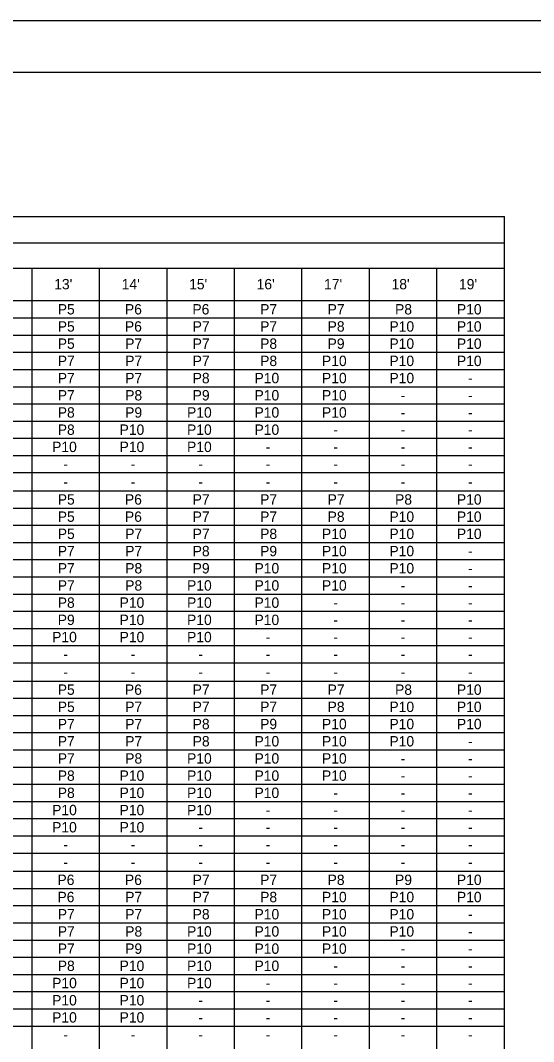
# Model space of a CAD drawing. Extents: x 637580 to 641008, y 294594 to 295782.
# Drawn here: x 639573.7 to 639722, y 295486.4 to 295781.6 of the extents above; entities that cross this region are included whole.
import ezdxf

# ---------------------------------------------------------------- set-up
doc = ezdxf.new("R2010")
doc.units = 0
for name, color, linetype in [('1', 7, 'Continuous'), ('2', 7, 'Continuous'), ('PLT-BNDY', 7, 'Continuous')]:
    doc.layers.add(name, color=color, linetype=linetype)

msp = doc.modelspace()

# ---------------------------------------------------------------- linework, layer by layer
at = {"layer": '1'}
for p, q in [((639302.31, 295766.63), (640088.31, 295766.63)), ((639346.67, 295724.98), (639713.6, 295724.98)), ((639713.6, 295260.68), (639713.6, 295724.98)), ((639346.67, 295717.3), (639713.6, 295717.3)), ((639346.67, 295700.6), (639713.6, 295700.6)), ((639346.67, 295645.61), (639713.6, 295645.61)), ((639346.67, 295590.62), (639713.6, 295590.62)), ((639346.67, 295535.63), (639713.6, 295535.63))]:
    msp.add_line(p, q, dxfattribs=at)
at = {"layer": '2'}
for p, q in [((639401.48, 295709.96), (639713.6, 295709.96)), ((639577.04, 295260.68), (639577.04, 295709.96)), ((639596.55, 295260.68), (639596.55, 295709.96)), ((639616.06, 295260.68), (639616.06, 295709.96)), ((639635.57, 295260.68), (639635.57, 295709.96)), ((639655.07, 295260.68), (639655.07, 295709.96)), ((639674.58, 295260.68), (639674.58, 295709.96)), ((639694.09, 295260.68), (639694.09, 295709.96)), ((639373.47, 295695.62), (639713.6, 295695.62)), ((639373.47, 295690.65), (639713.6, 295690.65)), ((639373.47, 295685.68), (639713.6, 295685.68)), ((639373.47, 295680.71), (639713.6, 295680.71)), ((639373.47, 295675.73), (639713.6, 295675.73)), ((639373.47, 295670.76), (639713.6, 295670.76)), ((639373.47, 295665.79), (639713.6, 295665.79)), ((639373.47, 295660.82), (639713.6, 295660.82)), ((639373.47, 295655.84), (639713.6, 295655.84)), ((639373.47, 295650.87), (639713.6, 295650.87)), ((639373.47, 295640.63), (639713.6, 295640.63)), ((639373.47, 295635.66), (639713.6, 295635.66)), ((639373.47, 295630.69), (639713.6, 295630.69)), ((639373.47, 295625.72), (639713.6, 295625.72)), ((639373.47, 295620.74), (639713.6, 295620.74)), ((639373.47, 295615.77), (639713.6, 295615.77)), ((639373.47, 295610.8), (639713.6, 295610.8)), ((639373.47, 295605.83), (639713.6, 295605.83)), ((639373.47, 295600.85), (639713.6, 295600.85)), ((639373.47, 295595.88), (639713.6, 295595.88)), ((639373.47, 295585.64), (639713.6, 295585.64)), ((639373.47, 295580.67), (639713.6, 295580.67)), ((639373.47, 295575.7), (639713.6, 295575.7)), ((639373.47, 295570.73), (639713.6, 295570.73)), ((639373.47, 295565.75), (639713.6, 295565.75)), ((639373.47, 295560.78), (639713.6, 295560.78)), ((639373.47, 295555.81), (639713.6, 295555.81)), ((639373.47, 295550.84), (639713.6, 295550.84)), ((639373.47, 295545.86), (639713.6, 295545.86)), ((639373.47, 295540.89), (639713.6, 295540.89)), ((639373.47, 295530.65), (639713.6, 295530.65)), ((639373.47, 295525.68), (639713.6, 295525.68)), ((639373.47, 295520.71), (639713.6, 295520.71)), ((639373.47, 295515.74), (639713.6, 295515.74)), ((639373.47, 295510.76), (639713.6, 295510.76)), ((639373.47, 295505.79), (639713.6, 295505.79)), ((639373.47, 295500.82), (639713.6, 295500.82)), ((639373.47, 295495.85), (639713.6, 295495.85)), ((639373.47, 295490.87), (639713.6, 295490.87))]:
    msp.add_line(p, q, dxfattribs=at)
at = {"layer": 'PLT-BNDY'}
msp.add_lwpolyline([(639262.31, 295781.63), (640103.31, 295781.63), (640103.31, 295187.63), (639262.31, 295187.63)], close=True, dxfattribs=at)

# ---------------------------------------------------------------- texts
at = {"layer": '1'}
for s, p in [("13'", (639583.43, 295703.87)), ("14'", (639602.94, 295703.87)), ("15'", (639622.44, 295703.87)), ("16'", (639641.95, 295703.87)), ("17'", (639661.46, 295703.87)), ("18'", (639680.97, 295703.87)), ("19'", (639700.47, 295703.87)), ('P5', (639584.45, 295696.61)), ('P6', (639603.87, 295696.61)), ('P6', (639623.38, 295696.61)), ('P7', (639642.97, 295696.61)), ('P7', (639662.48, 295696.61)), ('P8', (639681.98, 295696.61)), ('P10', (639699.86, 295696.61)), ('P5', (639584.45, 295691.64)), ('P6', (639603.87, 295691.64)), ('P7', (639623.46, 295691.64)), ('P7', (639642.97, 295691.64)), ('P8', (639662.48, 295691.64)), ('P10', (639680.35, 295691.64)), ('P10', (639699.86, 295691.64)), ('P5', (639584.45, 295686.67)), ('P7', (639603.95, 295686.67)), ('P7', (639623.46, 295686.67)), ('P8', (639642.97, 295686.67)), ('P9', (639662.47, 295686.67)), ('P10', (639680.35, 295686.67)), ('P10', (639699.86, 295686.67)), ('P7', (639584.45, 295681.69)), ('P7', (639603.95, 295681.69)), ('P7', (639623.46, 295681.69)), ('P8', (639642.97, 295681.69)), ('P10', (639660.85, 295681.69)), ('P10', (639680.35, 295681.69)), ('P10', (639699.86, 295681.69)), ('P7', (639584.45, 295676.72)), ('P7', (639603.95, 295676.72)), ('P8', (639623.46, 295676.72)), ('P10', (639641.34, 295676.72)), ('P10', (639660.85, 295676.72)), ('P10', (639680.35, 295676.72)), ('-', (639703.11, 295676.72)), ('P7', (639584.45, 295671.75)), ('P8', (639603.95, 295671.75)), ('P9', (639623.45, 295671.75)), ('P10', (639641.34, 295671.75)), ('P10', (639660.85, 295671.75)), ('-', (639683.6, 295671.75)), ('-', (639703.11, 295671.75)), ('P8', (639584.45, 295666.78)), ('P9', (639603.94, 295666.78)), ('P10', (639621.83, 295666.78)), ('P10', (639641.34, 295666.78)), ('P10', (639660.85, 295666.78)), ('-', (639683.6, 295666.78)), ('-', (639703.11, 295666.78)), ('P8', (639584.45, 295661.8)), ('P10', (639602.33, 295661.8)), ('P10', (639621.83, 295661.8)), ('P10', (639641.34, 295661.8)), ('-', (639664.1, 295661.8)), ('-', (639683.6, 295661.8)), ('-', (639703.11, 295661.8)), ('P10', (639582.82, 295656.83)), ('P10', (639602.33, 295656.83)), ('P10', (639621.83, 295656.83)), ('-', (639644.59, 295656.83)), ('-', (639664.1, 295656.83)), ('-', (639683.6, 295656.83)), ('-', (639703.11, 295656.83)), ('-', (639586.07, 295651.86)), ('-', (639605.57, 295651.86)), ('-', (639625.08, 295651.86)), ('-', (639644.59, 295651.86)), ('-', (639664.1, 295651.86)), ('-', (639683.6, 295651.86)), ('-', (639703.11, 295651.86)), ('-', (639586.07, 295646.74)), ('-', (639605.57, 295646.74)), ('-', (639625.08, 295646.74)), ('-', (639644.59, 295646.74)), ('-', (639664.1, 295646.74)), ('-', (639683.6, 295646.74)), ('-', (639703.11, 295646.74)), ('P5', (639584.45, 295641.62)), ('P6', (639603.87, 295641.62)), ('P7', (639623.46, 295641.62)), ('P7', (639642.97, 295641.62)), ('P7', (639662.48, 295641.62)), ('P8', (639681.98, 295641.62)), ('P10', (639699.86, 295641.62)), ('P5', (639584.45, 295636.65)), ('P6', (639603.87, 295636.65)), ('P7', (639623.46, 295636.65)), ('P7', (639642.97, 295636.65)), ('P8', (639662.48, 295636.65)), ('P10', (639680.35, 295636.65)), ('P10', (639699.86, 295636.65)), ('P5', (639584.45, 295631.68)), ('P7', (639603.95, 295631.68)), ('P7', (639623.46, 295631.68)), ('P8', (639642.97, 295631.68)), ('P10', (639660.85, 295631.68)), ('P10', (639680.35, 295631.68)), ('P10', (639699.86, 295631.68)), ('P7', (639584.45, 295626.7)), ('P7', (639603.95, 295626.7)), ('P8', (639623.46, 295626.7)), ('P9', (639642.96, 295626.7)), ('P10', (639660.85, 295626.7)), ('P10', (639680.35, 295626.7)), ('-', (639703.11, 295626.7)), ('P7', (639584.45, 295621.73)), ('P8', (639603.95, 295621.73)), ('P9', (639623.45, 295621.73)), ('P10', (639641.34, 295621.73)), ('P10', (639660.85, 295621.73)), ('P10', (639680.35, 295621.73)), ('-', (639703.11, 295621.73)), ('P7', (639584.45, 295616.76)), ('P8', (639603.95, 295616.76)), ('P10', (639621.83, 295616.76)), ('P10', (639641.34, 295616.76)), ('P10', (639660.85, 295616.76)), ('-', (639683.6, 295616.76)), ('-', (639703.11, 295616.76)), ('P8', (639584.45, 295611.79)), ('P10', (639602.33, 295611.79)), ('P10', (639621.83, 295611.79)), ('P10', (639641.34, 295611.79)), ('-', (639664.1, 295611.79)), ('-', (639683.6, 295611.79)), ('-', (639703.11, 295611.79)), ('P9', (639584.44, 295606.81)), ('P10', (639602.33, 295606.81)), ('P10', (639621.83, 295606.81)), ('P10', (639641.34, 295606.81)), ('-', (639664.1, 295606.81)), ('-', (639683.6, 295606.81)), ('-', (639703.11, 295606.81)), ('P10', (639582.82, 295601.84)), ('P10', (639602.33, 295601.84)), ('P10', (639621.83, 295601.84)), ('-', (639644.59, 295601.84)), ('-', (639664.1, 295601.84)), ('-', (639683.6, 295601.84)), ('-', (639703.11, 295601.84)), ('-', (639586.07, 295596.87)), ('-', (639605.57, 295596.87)), ('-', (639625.08, 295596.87)), ('-', (639644.59, 295596.87)), ('-', (639664.1, 295596.87)), ('-', (639683.6, 295596.87)), ('-', (639703.11, 295596.87)), ('-', (639586.07, 295591.75)), ('-', (639605.57, 295591.75)), ('-', (639625.08, 295591.75)), ('-', (639644.59, 295591.75)), ('-', (639664.1, 295591.75)), ('-', (639683.6, 295591.75)), ('-', (639703.11, 295591.75)), ('P5', (639584.45, 295586.63)), ('P6', (639603.87, 295586.63)), ('P7', (639623.46, 295586.63)), ('P7', (639642.97, 295586.63)), ('P7', (639662.48, 295586.63)), ('P8', (639681.98, 295586.63)), ('P10', (639699.86, 295586.63)), ('P5', (639584.45, 295581.66)), ('P7', (639603.95, 295581.66)), ('P7', (639623.46, 295581.66)), ('P7', (639642.97, 295581.66)), ('P8', (639662.48, 295581.66)), ('P10', (639680.35, 295581.66)), ('P10', (639699.86, 295581.66)), ('P7', (639584.45, 295576.69)), ('P7', (639603.95, 295576.69)), ('P8', (639623.46, 295576.69)), ('P9', (639642.96, 295576.69)), ('P10', (639660.85, 295576.69)), ('P10', (639680.35, 295576.69)), ('P10', (639699.86, 295576.69)), ('P7', (639584.45, 295571.71)), ('P7', (639603.95, 295571.71)), ('P8', (639623.46, 295571.71)), ('P10', (639641.34, 295571.71)), ('P10', (639660.85, 295571.71)), ('P10', (639680.35, 295571.71)), ('-', (639703.11, 295571.71)), ('P7', (639584.45, 295566.74)), ('P8', (639603.95, 295566.74)), ('P10', (639621.83, 295566.74)), ('P10', (639641.34, 295566.74)), ('P10', (639660.85, 295566.74)), ('-', (639683.6, 295566.74)), ('-', (639703.11, 295566.74)), ('P8', (639584.45, 295561.77)), ('P10', (639602.33, 295561.77)), ('P10', (639621.83, 295561.77)), ('P10', (639641.34, 295561.77)), ('P10', (639660.85, 295561.77)), ('-', (639683.6, 295561.77)), ('-', (639703.11, 295561.77)), ('P8', (639584.45, 295556.8)), ('P10', (639602.33, 295556.8)), ('P10', (639621.83, 295556.8)), ('P10', (639641.34, 295556.8)), ('-', (639664.1, 295556.8)), ('-', (639683.6, 295556.8)), ('-', (639703.11, 295556.8)), ('P10', (639582.82, 295551.82)), ('P10', (639602.33, 295551.82)), ('P10', (639621.83, 295551.82)), ('-', (639644.59, 295551.82)), ('-', (639664.1, 295551.82)), ('-', (639683.6, 295551.82)), ('-', (639703.11, 295551.82)), ('P10', (639582.82, 295546.85)), ('P10', (639602.33, 295546.85)), ('-', (639625.08, 295546.85)), ('-', (639644.59, 295546.85)), ('-', (639664.1, 295546.85)), ('-', (639683.6, 295546.85)), ('-', (639703.11, 295546.85)), ('-', (639586.07, 295541.88)), ('-', (639605.57, 295541.88)), ('-', (639625.08, 295541.88)), ('-', (639644.59, 295541.88)), ('-', (639664.1, 295541.88)), ('-', (639683.6, 295541.88)), ('-', (639703.11, 295541.88)), ('-', (639586.07, 295536.76)), ('-', (639605.57, 295536.76)), ('-', (639625.08, 295536.76)), ('-', (639644.59, 295536.76)), ('-', (639664.1, 295536.76)), ('-', (639683.6, 295536.76)), ('-', (639703.11, 295536.76)), ('P6', (639584.36, 295531.64)), ('P6', (639603.87, 295531.64)), ('P7', (639623.46, 295531.64)), ('P7', (639642.97, 295531.64)), ('P8', (639662.48, 295531.64)), ('P9', (639681.97, 295531.64)), ('P10', (639699.86, 295531.64)), ('P6', (639584.36, 295526.67)), ('P7', (639603.95, 295526.67)), ('P7', (639623.46, 295526.67)), ('P8', (639642.97, 295526.67)), ('P10', (639660.85, 295526.67)), ('P10', (639680.35, 295526.67)), ('P10', (639699.86, 295526.67)), ('P7', (639584.45, 295521.7)), ('P7', (639603.95, 295521.7)), ('P8', (639623.46, 295521.7)), ('P10', (639641.34, 295521.7)), ('P10', (639660.85, 295521.7)), ('P10', (639680.35, 295521.7)), ('-', (639703.11, 295521.7)), ('P7', (639584.45, 295516.72)), ('P8', (639603.95, 295516.72)), ('P10', (639621.83, 295516.72)), ('P10', (639641.34, 295516.72)), ('P10', (639660.85, 295516.72)), ('P10', (639680.35, 295516.72)), ('-', (639703.11, 295516.72)), ('P7', (639584.45, 295511.75)), ('P9', (639603.94, 295511.75)), ('P10', (639621.83, 295511.75)), ('P10', (639641.34, 295511.75)), ('P10', (639660.85, 295511.75)), ('-', (639683.6, 295511.75)), ('-', (639703.11, 295511.75)), ('P8', (639584.45, 295506.78)), ('P10', (639602.33, 295506.78)), ('P10', (639621.83, 295506.78)), ('P10', (639641.34, 295506.78)), ('-', (639664.1, 295506.78)), ('-', (639683.6, 295506.78)), ('-', (639703.11, 295506.78)), ('P10', (639582.82, 295501.81)), ('P10', (639602.33, 295501.81)), ('P10', (639621.83, 295501.81)), ('-', (639644.59, 295501.81)), ('-', (639664.1, 295501.81)), ('-', (639683.6, 295501.81)), ('-', (639703.11, 295501.81)), ('P10', (639582.82, 295496.83)), ('P10', (639602.33, 295496.83)), ('-', (639625.08, 295496.83)), ('-', (639644.59, 295496.83)), ('-', (639664.1, 295496.83)), ('-', (639683.6, 295496.83)), ('-', (639703.11, 295496.83)), ('P10', (639582.82, 295491.86)), ('P10', (639602.33, 295491.86)), ('-', (639625.08, 295491.86)), ('-', (639644.59, 295491.86)), ('-', (639664.1, 295491.86)), ('-', (639683.6, 295491.86)), ('-', (639703.11, 295491.86)), ('-', (639586.07, 295486.89)), ('-', (639605.57, 295486.89)), ('-', (639625.08, 295486.89)), ('-', (639644.59, 295486.89)), ('-', (639664.1, 295486.89)), ('-', (639683.6, 295486.89)), ('-', (639703.11, 295486.89))]:
    msp.add_text(s, height=3, dxfattribs=at).set_placement(p)

doc.saveas('drawing.dxf')
